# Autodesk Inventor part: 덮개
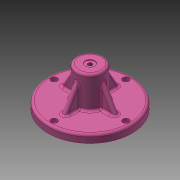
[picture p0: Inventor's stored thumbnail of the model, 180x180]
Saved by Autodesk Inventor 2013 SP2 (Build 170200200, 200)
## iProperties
Created: 2017-08
Part Number: 덮개
Material: 알루미늄 6061
Document SubType Name: Modeling
Designer: mduedu
Density: 2.71 g/cm^3
Mass: 331.485 g
Surface Area: 305.526 cm^2
Volume: 122.319 cm^3
Author: mduedu
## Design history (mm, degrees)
sketch "스케치1"
  geometry: C1 r 52.5 at (0, 0); 1 further point
  constraints: 1 centre point, 1 coincident
  dimensions: "d55" = 105 diameter of C1
extrude "돌출1" new body sketch "스케치1" distance "d5" = 10; taper "d6" = 0 deg
sketch "스케치2"
  geometry: C1 r 17 at (0, 0); 1 further point
  constraints: 1 centre point, 1 coincident
  dimensions: "d74" = 34 diameter of C1
extrude "돌출2" join sketch "스케치2" distance "d9" = 40; taper "d10" = 0 deg
sketch "스케치3"
  geometry: C1 r 37 at (0, 0); 1 further point
  constraints: 1 centre point, 1 coincident
  dimensions: "d56" = 74 diameter of C1
extrude "돌출3" join sketch "스케치3" distance "d12" = 8; taper "d13" = 0 deg
sketch "스케치4"
  geometry: C1 r 33 at (0, 0); 1 further point
  constraints: 1 centre point, 1 coincident
  dimensions: "d57" = 66 diameter of C1
extrude "돌출4" cut sketch "스케치4" distance "d16" = 7; taper "d17" = 0 deg
sketch "스케치5"
  geometry: C1 r 9 at (0, 0); 1 further point
  constraints: 1 centre point, 1 coincident
  dimensions: "d18" = 18 diameter of C1
extrude "돌출5" cut sketch "스케치5" distance "d19" = 47; taper "d20" = 0 deg
node "작업 평면1"
fillet "모깎기9" dims "d86" = 3
fillet "모깎기5" dims "d40" = 1
sketch "스케치12"
  geometry: C1 r 5 at (0, 0); 1 further point
  constraints: 1 centre point, 1 coincident
  dimensions: "d87" = 10 diameter of C1
extrude "돌출6" join sketch "스케치12" distance "d88" = 3; taper "d89" = 0 deg
fillet "모깎기10" dims "d91" = 1
chamfer "모따기1" distance "d41" = 1; stored, may be unused: second distance "d42" = 2, angle "d43" = 45 deg
fillet "모깎기7" dims "d45" = 3
fillet "모깎기8" dims "d46" = 3
sketch "스케치10" dims "d59" = 90
  geometry: 3 further points
  constraints: 2 vertical alignment, 1 coincident, 2 other
hole "구멍4" sketch "스케치10" at (0, 45) diameter "d60" = 4.5; stored, may be unused: countersink angle "d64" = 90 deg, drill point angle "d66" = 118 deg; dims "d61" = 6, "d62" = 8, "d63" = 4.6, "d65" = 8
sketch "스케치13"
  geometry: L1 (52.5, 7)-(52.5, 0) reference; L2 (52.5, 0)-(47.25, 0) reference; L3 (47.25, 0)-(47.25, 5.4) reference; L4 (47.25, 5.4)-(49, 5.4) reference; L5 (49, 5.4)-(49, 10) reference; L6 (49, 10)-(49.5, 10) reference; L7 (-49.5, 10)-(-49, 10) reference; L8 (-49, 10)-(-49, 5.4) reference; L9 (-49, 5.4)-(-47.25, 5.4) reference; L10 (-47.25, 5.4)-(-47.25, 0) reference; L11 (-47.25, 0)-(-52.5, 0) reference; L12 (-52.5, 0)-(-52.5, 7) reference; L13 (-6, 46)-(-8, 46) reference; L14 (-9, 45)-(-9, -1) reference; L15 (-9, -1)-(-30, -1) reference; L16 (-33, -4)-(-33, -8) reference; L17 (-33, -8)-(-36, -8) reference; L18 (-36, -8)-(-37, -7) reference; L19 (-37, -7)-(-37, 0) reference; L20 (-37, 0)-(-42.75, 0) reference; L21 (-42.75, 0)-(-42.75, 5.4) reference; L22 (-42.75, 5.4)-(-41, 5.4) reference; L23 (-41, 5.4)-(-41, 10) reference; L24 (-41, 10)-(-20, 10) reference; L25 (-17, 13)-(-17, 47) reference; L26 (-14, 50)-(14, 50) reference; L27 (17, 47)-(17, 13) reference; L28 (20, 10)-(41, 10) reference; L29 (41, 10)-(41, 5.4) reference; L30 (41, 5.4)-(42.75, 5.4) reference; L31 (42.75, 5.4)-(42.75, 0) reference; L32 (42.75, 0)-(37, 0) reference; L33 (37, 0)-(37, -7) reference; L34 (37, -7)-(36, -8) reference; L35 (36, -8)-(33, -8) reference; L36 (33, -8)-(33, -4) reference; L37 (30, -1)-(9, -1) reference; L38 (9, -1)-(9, 45) reference; L39 (8, 46)-(6, 46) reference; L40 (5, 45)-(5, 43) reference; L41 (5, 43)-(-5, 43) reference; L42 (-5, 43)-(-5, 45) reference; L43 (17, 40)-(34.321, 10); L44 (-49.5, 10)-(49.5, 10) reference; A1 r 3 centre (49.5, 7) between (52.5, 7) and (49.5, 10) reference; A2 r 3 centre (-49.5, 7) between (-49.5, 10) and (-52.5, 7) reference; A3 r 1 centre (-6, 45) between (-5, 45) and (-6, 46) reference; A4 r 1 centre (-8, 45) between (-8, 46) and (-9, 45) reference; A5 r 3 centre (-30, -4) between (-30, -1) and (-33, -4) reference; A6 r 3 centre (-20, 13) between (-20, 10) and (-17, 13) reference; A7 r 3 centre (-14, 47) between (-14, 50) and (-17, 47) reference; A8 r 3 centre (14, 47) between (17, 47) and (14, 50) reference; A9 r 3 centre (20, 13) between (17, 13) and (20, 10) reference; A10 r 3 centre (30, -4) between (33, -4) and (30, -1) reference; A11 r 1 centre (8, 45) between (9, 45) and (8, 46) reference; A12 r 1 centre (6, 45) between (6, 46) and (5, 45) reference; 1 further point
  constraints: 2 end point, 2 point on line
  dimensions: "d98" = 120 deg angle of L43 L28; "d99" = 30 distance from line of L43.start L44
feature "리브1" sketch "스케치13" dims "d100" = 1, "d101" = 6, "d102" = 0, "d103" = 0, "d104" = 1, "d105" = 1
fillet "모깎기11" dims "d106" = 3
fillet "모깎기12" dims "d107" = 3
hole "구멍6" diameter "d115" = 5.242; stored, may be unused: countersink angle "d119" = 90 deg, drill point angle "d121" = 118 deg; dims "d116" = 6, "d117" = 12, "d118" = 1, "d120" = 8, "d122" = 10, "d123" = 10
node "솔리드1"
pattern_circular "원형 패턴1" dims angle "d68" = 360 deg
pattern_circular "원형 패턴2" dims "d109" = 270 deg
node "절단 모서리 투영1"
